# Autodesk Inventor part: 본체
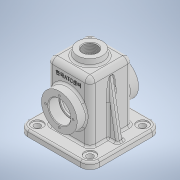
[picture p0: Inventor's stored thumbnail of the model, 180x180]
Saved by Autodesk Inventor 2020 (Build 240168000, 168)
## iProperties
Created: 2021-07
Part Number: 본체
Material: 일반
Document SubType Name: Modeling
Designer: Owner
Density: 1 g/cm^3
Appearance: 기본값
Mass: 278.261 g
Surface Area: 858.222 cm^2
Volume: 278.261 cm^3
Author: Owner
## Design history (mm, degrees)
sketch "스케치1"
  geometry: L1 (-34, 34)-(34, 34); L2 (34, 34)-(34, -34); L3 (34, -34)-(-34, -34); L4 (-34, -34)-(-34, 34); L5 (-34, 34)-(34, -34); L6 (34, 34)-(-34, -34); 1 further point
  constraints: 12 end point, 2 midpoint, 2 parallel, 1 horizontal, 1 perpendicular
  dimensions: "d0" = 68 distance of L2.end L3.end; "d1" = 68 distance of L1.end L2.end
extrude "돌출1" new body sketch "스케치1" distance "d2" = 105; taper "d3" = 0 deg
fillet "모깎기1" dims "d4" = 8
fillet "모깎기2" dims "d5" = 8
feature "쉘1" dims "d6" = 5
node "작업 평면1"
sketch "스케치2"
  geometry: C1 r 20 at (0, 0); 1 further point
  constraints: 1 centre point, 1 coincident
  dimensions: "d8" = 40 diameter of C1
extrude "돌출2" join sketch "스케치2" stored distance "d9" = 105; taper "d10" = 8 deg
sketch "스케치3"
  geometry: L1 (57, -57)-(-57, -57); L2 (-57, -57)-(-57, 57); L3 (-57, 57)-(57, 57); L4 (57, 57)-(57, -57); L5 (57, -57)-(-57, 57); L6 (-57, -57)-(57, 57); L7 (29, 26)-(29, -26) reference; L8 (34, 26)-(34, -26) reference; L9 (-26, 34)-(26, 34) reference; L10 (-34, -26)-(-34, 26) reference; L11 (26, -29)-(-26, -29) reference; L12 (-29, -26)-(-29, 26) reference; L13 (-26, 29)-(26, 29) reference; L14 (29, 26)-(29, -26) reference; L15 (26, -34)-(-26, -34) reference; L16 (34, 26)-(34, -26) reference; L17 (-26, 34)-(26, 34) reference; L18 (-34, -26)-(-34, 26) reference; A1 r 8 centre (26, 26) between (34, 26) and (26, 34) reference; A2 r 8 centre (-26, 26) between (-26, 34) and (-34, 26) reference; A3 r 3 centre (-26, -26) between (-29, -26) and (-26, -29) reference; A4 r 3 centre (-26, 26) between (-26, 29) and (-29, 26) reference; A5 r 3 centre (26, 26) between (29, 26) and (26, 29) reference; A6 r 3 centre (26, -26) between (26, -29) and (29, -26) reference; A7 r 8 centre (26, -26) between (26, -34) and (34, -26) reference; A8 r 8 centre (26, 26) between (34, 26) and (26, 34) reference; A9 r 8 centre (-26, 26) between (-26, 34) and (-34, 26) reference; A10 r 8 centre (-26, -26) between (-34, -26) and (-26, -34) reference; 3 further points
  constraints: 12 end point, 2 midpoint, 2 parallel, 1 horizontal, 1 perpendicular
  dimensions: "d11" = 114 distance of L2.end L3.end; "d12" = 114 distance of L1.end L2.end
extrude "돌출3" join sketch "스케치3" distance "d13" = 10; taper "d14" = 0 deg
fillet "모깎기3" dims "d15" = 15
node "작업 평면2"
sketch "스케치4"
  geometry: L1 (-31, -97)-(-16, -97) reference; L2 (-16, -97)-(-31, -97) reference; L3 (-16, -97)-(68, -97) reference; L4 (83, -97)-(68, -97) reference; L5 (68, -97)-(83, -97) reference; L6 (68, -97)-(-16, -97) reference; L7 (46, 18)-(6, 18) reference; C1 r 28.5 at (26, -45); 3 further points
  constraints: 2 midpoint, 1 centre point, 1 vertical alignment
  dimensions: "d17" = 52 distance from line of C1.centre L3; "d18" = 57 diameter of C1
extrude "돌출4" join sketch "스케치4" stored distance "d19" = 105; taper "d20" = 0 deg
sketch "스케치5"
  geometry: C1 r 28.5 at (0, 0) reference; C2 r 17.5 at (0, 0); 1 further point
  constraints: 1 centre point, 1 coincident
  dimensions: "d21" = 35 diameter of C2
extrude "돌출5" cut sketch "스케치5" distance "d22" = 17; taper "d23" = 0 deg
sketch "스케치6"
  geometry: C1 r 17.5 at (0, 0) reference; C2 r 15 at (0, 0); 1 further point
  constraints: 1 centre point, 1 coincident
  dimensions: "d24" = 30 diameter of C2
extrude "돌출6" cut sketch "스케치6" distance "d25" = 3; taper "d26" = 0 deg
sketch "스케치8"
  geometry: C1 r 20 at (0, 0) reference; 2 further points
  constraints: 1 coincident
hole "구멍1" sketch "스케치8" at (0, 0) diameter "d27" = 22.83494; stored, may be unused: countersink angle "d31" = 90 deg, drill point angle "d33" = 0 deg; dims "d28" = 50, "d29" = 11, "d30" = 2, "d32" = 59.3
sketch "스케치9" dims "d34" = 44
  geometry: C1 r 28.5 at (0, 0) reference; 3 further points
  constraints: 2 vertical alignment, 1 coincident, 2 other
hole "구멍2" sketch "스케치9" at (0, 22) diameter "d35" = 3.242; stored, may be unused: countersink angle "d39" = 90 deg, drill point angle "d41" = 118 deg; dims "d36" = 8, "d37" = 11, "d38" = 2, "d40" = 10
sketch "스케치10"
  geometry: A1 r 15 centre (42, -42) between (42, -57) and (57, -42) reference; A2 r 15 centre (42, 42) between (57, 42) and (42, 57) reference; A3 r 15 centre (-42, -42) between (-57, -42) and (-42, -57) reference; A4 r 15 centre (-42, 42) between (-42, 57) and (-57, 42) reference; 5 further points
  constraints: 4 coincident
hole "구멍3" sketch "스케치10" at (42, -42), (42, 42), (-42, -42), (-42, 42) diameter "d45" = 10; stored, may be unused: countersink angle "d49" = 90 deg, drill point angle "d51" = 118 deg; dims "d46" = 8, "d47" = 18, "d48" = 2, "d50" = 10
sketch "스케치11"
  geometry: L1 (-39.685, 62.828)-(-49, 10); L2 (-57, 10)-(-42, 10) reference; L3 (-57, 10)-(-57, 0) reference; L4 (-57, 0)-(-57, 10) reference; 1 further point
  constraints: 2 end point, 1 point on line
  dimensions: "d52" = 8 distance of L2.start L1.end; "d53" = 10 deg angle of L3 L1
feature "리브1" sketch "스케치11" dims "d54" = 1, "d55" = 10, "d56" = 0, "d57" = 0, "d58" = 1, "d59" = 1
fillet "모깎기4" dims "d60" = 3
fillet "모깎기6" dims "d62" = 3
fillet "모깎기7" dims "d63" = 3
fillet "모깎기8" dims "d64" = 3
fillet "모깎기9" dims "d65" = 3
chamfer "모따기1" distance "d66" = 1; stored, may be unused: second distance "d67" = 2, angle "d68" = 45 deg
chamfer "모따기2" distance "d69" = 1; stored, may be unused: second distance "d70" = 2, angle "d71" = 45 deg
fillet "모깎기10" dims "d72" = 0.3
sketch "스케치12"
  geometry: L1 (46, 18)-(6, 18) reference; C1 r 28.5 at (26, -45) reference; 2 further points
  constraints: 1 vertical alignment, 1 other
  dimensions: "d73" = 25 distance from line of L1 point (26, -7)
feature "엠보싱1" sketch "스케치12" dims "d0" = 68, "d1" = 68, "d74" = 0.5, "d75" = 0
node "솔리드1"
mirror "미러1"
pattern_circular "원형 패턴1" dims angle "d43" = 360 deg
mirror "미러2"
mirror "미러3"
node "투영된 루프1"
node "투영된 루프2"
node "투영된 루프3"
node "투영된 루프4"
node "투영된 루프5"
feature "A9D066F2-1C7D-4E18-AEED-F7BC21143FA4" dims "d45" = 10, "d46" = 8, "d47" = 18, "d48" = 2, "d49" = 90 deg, "d50" = 10, "d51" = 118 deg
other parameters: "d7" = 115, "d16" = 15
